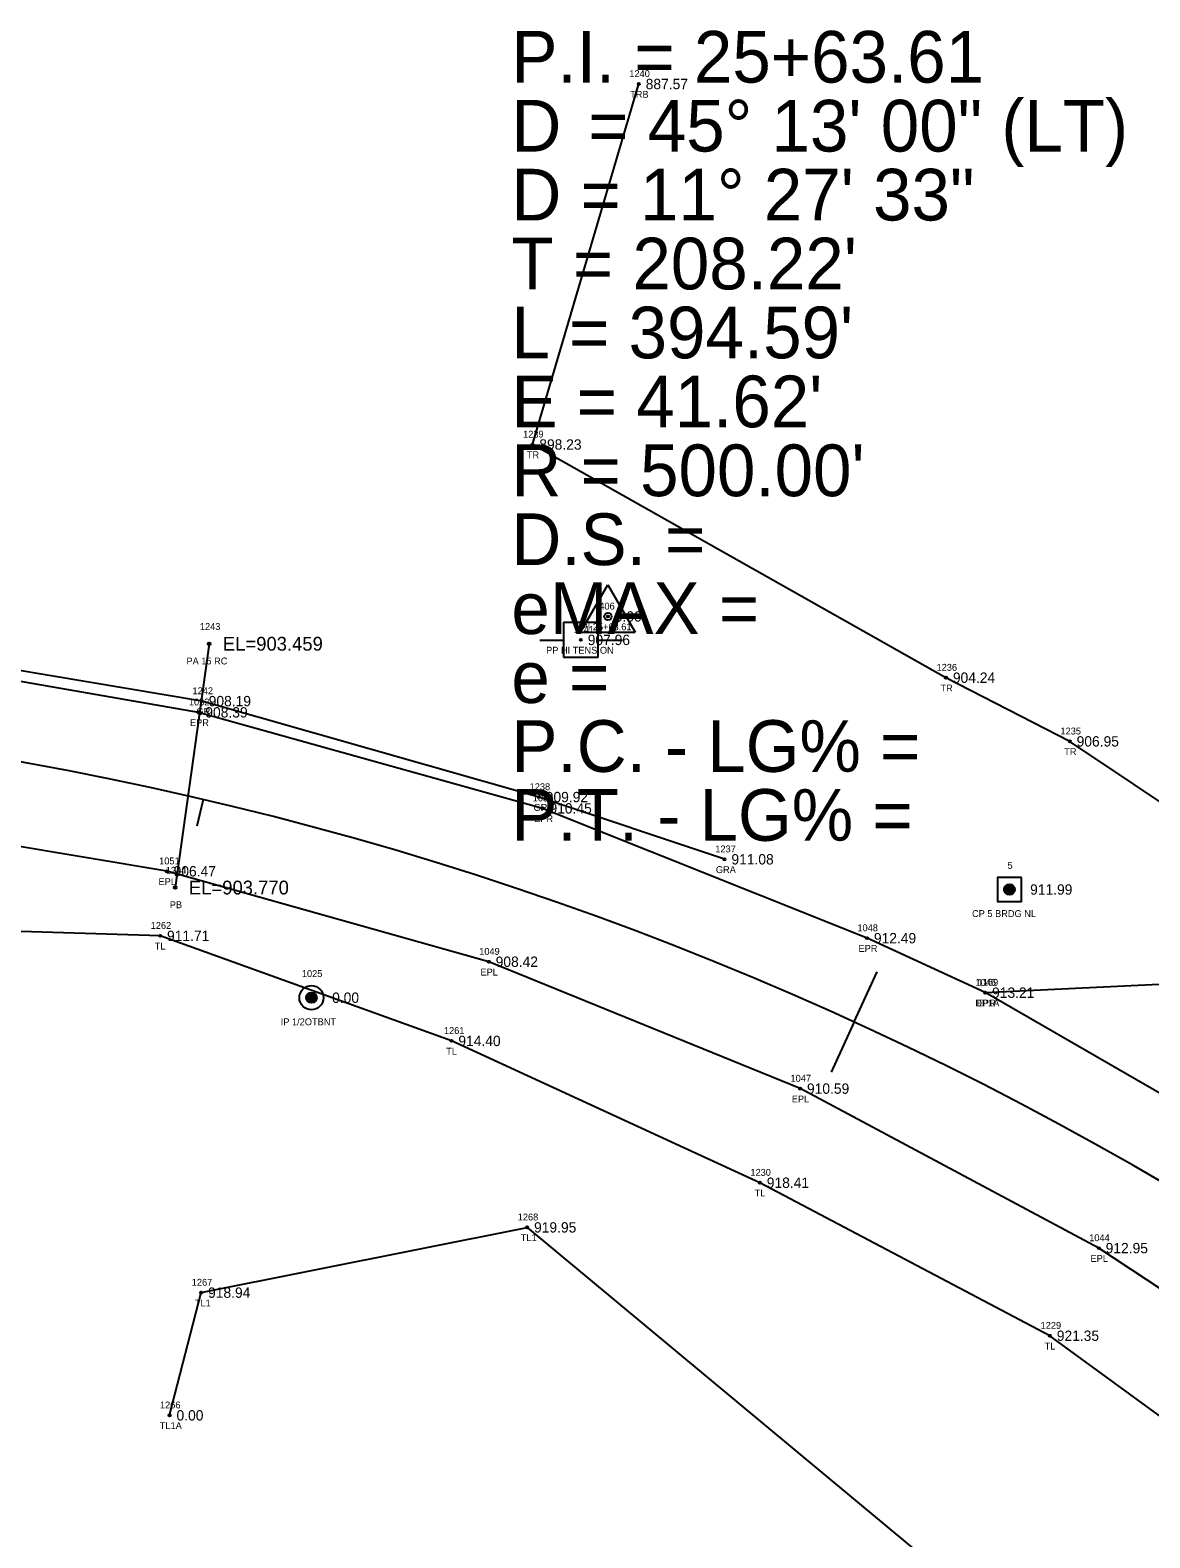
# Model space of a CAD drawing. Extents: x 1393163 to 1398407, y 1072670 to 1074651.
# Drawn here: x 1396650.2 to 1396812.6, y 1074266.9 to 1074485.6 of the extents above; entities that cross this region are included whole.
import ezdxf

# ---------------------------------------------------------------- set-up
doc = ezdxf.new("R2010")
doc.units = 0
for name, color, linetype in [('RD_EX_DR_Pipe', 7, 'Continuous'), ('RD_EX_DR_Pipe_txCode', 7, 'Continuous'), ('RD_EX_Driveway', 7, 'Continuous'), ('RD_EX_Driveway_txCode', 7, 'Continuous'), ('RD_EX_DV_Prop_txCode', 7, 'Continuous'), ('RD_EX_DV_PropPin', 7, 'Continuous'), ('RD_EX_GuardRail', 7, 'Continuous'), ('RD_EX_GuardRail_txCode', 7, 'Continuous'), ('RD_EX_Road', 7, 'Continuous'), ('RD_EX_Road_txCode', 7, 'Continuous'), ('RD_EX_TX_Driveway_ELEV', 7, 'Continuous'), ('RD_EX_TX_DV_Prop_ELEV', 7, 'Continuous'), ('RD_EX_TX_GuardRail_ELEV', 7, 'Continuous'), ('RD_EX_TX_Road_ELEV', 7, 'Continuous'), ('RD_EX_TX_VEG_ELEV', 7, 'Continuous'), ('RD_EX_UT', 7, 'Continuous'), ('RD_EX_UT_txCode', 7, 'Continuous'), ('RD_EX_VEG', 7, 'Continuous'), ('RD_EX_VEG_txCode', 7, 'Continuous'), ('RD_HC_Cl', 7, 'Continuous'), ('RD_HC_Data', 7, 'Continuous'), ('RD_HC_Data_Tic', 7, 'Continuous'), ('RD_HC_Survey', 7, 'Continuous'), ('RD_HC_Survey_ELEV', 7, 'Continuous'), ('RD_HC_Survey_txCode', 7, 'Continuous'), ('RD_HC_txCode', 7, 'Continuous'), ('RD_SMD_Locator', 7, 'Continuous'), ('RD_TX_Pipe_ElevEX', 7, 'Continuous')]:
    doc.layers.add(name, color=color, linetype=linetype)

msp = doc.modelspace()

# ---------------------------------------------------------------- linework, layer by layer
at = {"layer": 'RD_EX_DR_Pipe'}
msp.add_line((1396676.14, 1074396.59), (1396671.21, 1074361.22), dxfattribs=at)
at = {"layer": 'RD_EX_Driveway'}
msp.add_lwpolyline([(1396788.75, 1074345.97), (1396814, 1074347.19), (1396845.44, 1074351.21), (1396872.44, 1074348.53), (1396900.89, 1074337.89), (1396935.17, 1074321.37), (1396975.52, 1074301.17), (1397009.08, 1074288.99), (1397048.05, 1074289.01)], dxfattribs=at)
at = {"layer": 'RD_EX_DV_PropPin'}
for p, q in [((1396690.25, 1074345.04), (1396690.25, 1074345.43)), ((1396690.29, 1074344.94), (1396690.29, 1074345.53)), ((1396690.32, 1074344.87), (1396690.32, 1074345.61)), ((1396690.36, 1074344.81), (1396690.36, 1074345.66)), ((1396690.39, 1074344.76), (1396690.39, 1074345.71)), ((1396690.43, 1074344.72), (1396690.43, 1074345.75)), ((1396690.46, 1074344.69), (1396690.46, 1074345.79)), ((1396690.5, 1074344.65), (1396690.5, 1074345.82)), ((1396690.53, 1074344.63), (1396690.53, 1074345.85)), ((1396690.57, 1074344.6), (1396690.57, 1074345.87)), ((1396690.6, 1074344.58), (1396690.6, 1074345.89)), ((1396690.64, 1074344.56), (1396690.64, 1074345.91)), ((1396690.67, 1074344.54), (1396690.67, 1074345.93)), ((1396690.71, 1074344.53), (1396690.71, 1074345.94)), ((1396690.74, 1074344.52), (1396690.74, 1074345.96)), ((1396690.78, 1074344.5), (1396690.78, 1074345.97)), ((1396690.81, 1074344.5), (1396690.81, 1074345.98)), ((1396690.85, 1074344.49), (1396690.85, 1074345.98)), ((1396690.88, 1074344.48), (1396690.88, 1074345.99)), ((1396690.92, 1074344.48), (1396690.92, 1074345.99)), ((1396690.95, 1074344.48), (1396690.95, 1074346)), ((1396690.99, 1074344.47), (1396690.99, 1074346)), ((1396691.02, 1074344.48), (1396691.02, 1074346)), ((1396691.06, 1074344.48), (1396691.06, 1074345.99)), ((1396691.1, 1074344.48), (1396691.1, 1074345.99)), ((1396691.13, 1074344.49), (1396691.13, 1074345.98)), ((1396691.17, 1074344.5), (1396691.17, 1074345.98)), ((1396691.2, 1074344.5), (1396691.2, 1074345.97)), ((1396691.24, 1074344.52), (1396691.24, 1074345.96)), ((1396691.27, 1074344.53), (1396691.27, 1074345.94)), ((1396691.31, 1074344.54), (1396691.31, 1074345.93)), ((1396691.34, 1074344.56), (1396691.34, 1074345.91)), ((1396691.38, 1074344.58), (1396691.38, 1074345.89)), ((1396691.41, 1074344.6), (1396691.41, 1074345.87)), ((1396691.45, 1074344.63), (1396691.45, 1074345.85)), ((1396691.48, 1074344.65), (1396691.48, 1074345.82)), ((1396691.52, 1074344.69), (1396691.52, 1074345.79)), ((1396691.55, 1074344.72), (1396691.55, 1074345.75)), ((1396691.59, 1074344.76), (1396691.59, 1074345.71)), ((1396691.62, 1074344.81), (1396691.62, 1074345.66)), ((1396691.66, 1074344.87), (1396691.66, 1074345.61)), ((1396691.69, 1074344.94), (1396691.69, 1074345.53)), ((1396691.73, 1074345.04), (1396691.73, 1074345.43))]:
    msp.add_line(p, q, dxfattribs=at)
for radius in [1.75, 0.761]:
    msp.add_circle((1396690.99, 1074345.24), radius, dxfattribs=at)
at = {"layer": 'RD_EX_GuardRail'}
msp.add_lwpolyline([(1396750.93, 1074365.32), (1396723.99, 1074374.35), (1396675.08, 1074388.27), (1396625.55, 1074396.6), (1396572.93, 1074399.71), (1396523.21, 1074399.14), (1396473.17, 1074396.16), (1396421.53, 1074392.08), (1396371.98, 1074385.73), (1396321.51, 1074375.41), (1396279.87, 1074364.31)], dxfattribs=at)
at = {"layer": 'RD_EX_Road'}
for points in [[(1397127.02, 1074075.08), (1397087.96, 1074107.09), (1397050.33, 1074139.1), (1397012.08, 1074172.65), (1396975.18, 1074205.06), (1396938.56, 1074237.05), (1396899.33, 1074270.29), (1396859.1, 1074302.06), (1396826.71, 1074324.07), (1396788.75, 1074345.97), (1396771.6, 1074353.88), (1396724.53, 1074372.71), (1396674.59, 1074386.64), (1396624.89, 1074395.26)], [(1397113.03, 1074055.78), (1397073.45, 1074088.2), (1397033.12, 1074122.53), (1397005.07, 1074146.99), (1396959.64, 1074187.05), (1396921.5, 1074220.1), (1396884.1, 1074252.26), (1396844.62, 1074282.93), (1396805.23, 1074308.91), (1396761.89, 1074332.05), (1396716.72, 1074350.46), (1396669.99, 1074363.58), (1396621.68, 1074371.65)]]:
    msp.add_lwpolyline(points, dxfattribs=at)
at = {"layer": 'RD_EX_UT'}
for p, q in [((1396732.57, 1074399.66), (1396727.57, 1074399.66)), ((1396727.57, 1074399.66), (1396727.57, 1074394.66)), ((1396732.57, 1074394.66), (1396732.57, 1074399.66)), ((1396724.14, 1074397.1), (1396727.61, 1074397.1)), ((1396732.5, 1074397.1), (1396736.14, 1074397.1)), ((1396727.57, 1074394.66), (1396732.57, 1074394.66))]:
    msp.add_line(p, q, dxfattribs=at)
at = {"layer": 'RD_EX_VEG'}
for points in [[(1397009.65, 1074291.54), (1396903.78, 1074340.47), (1396857.31, 1074355.57), (1396838.07, 1074357.65), (1396801.02, 1074382.43), (1396783.06, 1074391.67), (1396723.05, 1074425.5), (1396738.49, 1074477.8)], [(1396894.17, 1074168.98), (1396933.03, 1074155.57), (1396955.02, 1074151.42), (1396964.49, 1074163.23), (1396875.81, 1074239.54), (1396798.14, 1074296.2), (1396756.06, 1074318.4), (1396711.3, 1074338.97), (1396669.03, 1074354.22), (1396616.02, 1074355.85)], [(1396670.41, 1074284.65), (1396674.99, 1074302.45), (1396722.29, 1074311.92), (1396894.17, 1074168.98)]]:
    msp.add_lwpolyline(points, dxfattribs=at)
at = {"layer": 'RD_HC_Cl'}
msp.add_arc((1396561.57, 1073887.11), 500, 48.8271, 94.0437, dxfattribs=at)
at = {"layer": 'RD_HC_Data'}
for p, q in [((1396730.03, 1074398.26), (1396734.01, 1074405.14)), ((1396734.01, 1074405.14), (1396737.97, 1074398.26)), ((1396730.03, 1074398.26), (1396737.97, 1074398.26))]:
    msp.add_line(p, q, dxfattribs=at)
msp.add_circle((1396734.01, 1074400.55), 0.529, dxfattribs=at)
at = {"layer": 'RD_HC_Data_Tic'}
for p, q in [((1396675.26, 1074374.01), (1396674.35, 1074370.12)), ((1396769.73, 1074341.72), (1396773.06, 1074348.99)), ((1396769.73, 1074341.72), (1396766.4, 1074334.45))]:
    msp.add_line(p, q, dxfattribs=at)
at = {"layer": 'RD_HC_Survey'}
for p, q in [((1396791.52, 1074360.76), (1396791.52, 1074361.12)), ((1396791.55, 1074360.68), (1396791.55, 1074361.2)), ((1396791.57, 1074360.62), (1396791.57, 1074361.26)), ((1396791.6, 1074360.57), (1396791.6, 1074361.31)), ((1396791.62, 1074360.53), (1396791.62, 1074361.36)), ((1396791.64, 1074360.49), (1396791.64, 1074361.39)), ((1396791.67, 1074360.46), (1396791.67, 1074361.42)), ((1396791.69, 1074360.43), (1396791.69, 1074361.45)), ((1396791.72, 1074360.4), (1396791.72, 1074361.48)), ((1396791.74, 1074360.38), (1396791.74, 1074361.5)), ((1396791.77, 1074360.36), (1396791.77, 1074361.53)), ((1396791.79, 1074360.34), (1396791.79, 1074361.55)), ((1396791.82, 1074360.32), (1396791.82, 1074361.57)), ((1396791.84, 1074360.3), (1396791.84, 1074361.58)), ((1396791.87, 1074360.29), (1396791.87, 1074361.6)), ((1396791.89, 1074360.27), (1396791.89, 1074361.61)), ((1396791.92, 1074360.26), (1396791.92, 1074361.63)), ((1396791.94, 1074360.25), (1396791.94, 1074361.64)), ((1396791.97, 1074360.23), (1396791.97, 1074361.65)), ((1396791.99, 1074360.22), (1396791.99, 1074361.66)), ((1396792.02, 1074360.22), (1396792.02, 1074361.67)), ((1396792.04, 1074360.21), (1396792.04, 1074361.68)), ((1396792.07, 1074360.2), (1396792.07, 1074361.68)), ((1396792.09, 1074360.19), (1396792.09, 1074361.69)), ((1396792.12, 1074360.19), (1396792.12, 1074361.7)), ((1396792.14, 1074360.18), (1396792.14, 1074361.7)), ((1396792.16, 1074360.18), (1396792.16, 1074361.7)), ((1396792.19, 1074360.18), (1396792.19, 1074361.71)), ((1396792.21, 1074360.17), (1396792.21, 1074361.71)), ((1396792.24, 1074360.17), (1396792.24, 1074361.71)), ((1396792.26, 1074360.17), (1396792.26, 1074361.71)), ((1396792.29, 1074360.17), (1396792.29, 1074361.71)), ((1396792.31, 1074360.17), (1396792.31, 1074361.71)), ((1396792.34, 1074360.18), (1396792.34, 1074361.71)), ((1396792.36, 1074360.18), (1396792.36, 1074361.71)), ((1396792.39, 1074360.18), (1396792.39, 1074361.7)), ((1396792.41, 1074360.19), (1396792.41, 1074361.7)), ((1396792.44, 1074360.19), (1396792.44, 1074361.69)), ((1396792.46, 1074360.2), (1396792.46, 1074361.69)), ((1396792.49, 1074360.2), (1396792.49, 1074361.68)), ((1396792.51, 1074360.21), (1396792.51, 1074361.67)), ((1396792.54, 1074360.22), (1396792.54, 1074361.66)), ((1396792.56, 1074360.23), (1396792.56, 1074361.65)), ((1396792.59, 1074360.24), (1396792.59, 1074361.64)), ((1396792.61, 1074360.25), (1396792.61, 1074361.63)), ((1396792.63, 1074360.27), (1396792.63, 1074361.62)), ((1396792.66, 1074360.28), (1396792.66, 1074361.61)), ((1396792.68, 1074360.29), (1396792.68, 1074361.59)), ((1396792.71, 1074360.31), (1396792.71, 1074361.57)), ((1396792.73, 1074360.33), (1396792.73, 1074361.56)), ((1396792.76, 1074360.35), (1396792.76, 1074361.54)), ((1396792.78, 1074360.37), (1396792.78, 1074361.52)), ((1396792.81, 1074360.39), (1396792.81, 1074361.49)), ((1396792.83, 1074360.42), (1396792.83, 1074361.47)), ((1396792.86, 1074360.45), (1396792.86, 1074361.44)), ((1396792.88, 1074360.48), (1396792.88, 1074361.41)), ((1396792.91, 1074360.51), (1396792.91, 1074361.37)), ((1396792.93, 1074360.55), (1396792.93, 1074361.33)), ((1396792.96, 1074360.6), (1396792.96, 1074361.29)), ((1396792.98, 1074360.65), (1396792.98, 1074361.23)), ((1396793.01, 1074360.72), (1396793.01, 1074361.16)), ((1396793.03, 1074360.83), (1396793.03, 1074361.05))]:
    msp.add_line(p, q, dxfattribs=at)
msp.add_lwpolyline([(1396794.02, 1074362.69), (1396790.52, 1074362.69), (1396790.52, 1074359.19), (1396794.02, 1074359.19)], close=True, dxfattribs=at)
msp.add_circle((1396792.27, 1074360.94), 0.769, dxfattribs=at)
at = {"layer": 'RD_SMD_Locator'}
for centre, radius in [((1396738.49, 1074477.8), 0.15), ((1396723.05, 1074425.5), 0.15), ((1396734.01, 1074400.55), 0.15), ((1396730.08, 1074397.15), 0.15), ((1396676.14, 1074396.59), 0.2), ((1396783.06, 1074391.67), 0.15), ((1396675.08, 1074388.27), 0.15), ((1396674.59, 1074386.64), 0.15), ((1396801.02, 1074382.43), 0.15), ((1396723.99, 1074374.35), 0.15), ((1396724.53, 1074372.71), 0.15), ((1396750.93, 1074365.32), 0.15), ((1396669.99, 1074363.58), 0.15), ((1396671.21, 1074361.22), 0.2), ((1396792.27, 1074360.94), 0.15), ((1396669.03, 1074354.22), 0.15), ((1396771.6, 1074353.88), 0.15), ((1396716.72, 1074350.46), 0.15), ((1396690.99, 1074345.24), 0.15), ((1396788.75, 1074345.97), 0.15), ((1396788.75, 1074345.97), 0.15), ((1396711.3, 1074338.97), 0.15), ((1396761.89, 1074332.05), 0.15), ((1396756.06, 1074318.4), 0.15), ((1396722.29, 1074311.92), 0.15), ((1396805.23, 1074308.91), 0.15), ((1396674.99, 1074302.45), 0.15), ((1396798.14, 1074296.2), 0.15), ((1396670.41, 1074284.65), 0.15)]:
    msp.add_circle(centre, radius, dxfattribs=at)

# ---------------------------------------------------------------- texts
at = {"layer": 'RD_EX_DR_Pipe_txCode'}
for s, p in [('1243', (1396674.8, 1074398.59)), ('PA 15 RC', (1396672.85, 1074393.59)), ('1244', (1396669.86, 1074363.22)), ('PB', (1396670.43, 1074358.22))]:
    msp.add_text(s, height=1, dxfattribs=at).set_placement(p)
at = {"layer": 'RD_EX_Driveway_txCode'}
for s, p in [('1169', (1396787.66, 1074346.97)), ('DP1A', (1396787.31, 1074343.97))]:
    msp.add_text(s, height=1, dxfattribs=at).set_placement(p)
at = {"layer": 'RD_EX_DV_Prop_txCode'}
for s, p in [('1025', (1396689.6, 1074348.24)), ('IP 1/2OTBNT', (1396686.53, 1074341.24))]:
    msp.add_text(s, height=1, dxfattribs=at).set_placement(p)
at = {"layer": 'RD_EX_GuardRail_txCode'}
for s, p in [('1242', (1396673.73, 1074389.27)), ('GR', (1396674.3, 1074386.27)), ('1238', (1396722.65, 1074375.35)), ('GR', (1396723.21, 1074372.35)), ('1237', (1396749.59, 1074366.32)), ('GRA', (1396749.67, 1074363.32))]:
    msp.add_text(s, height=1, dxfattribs=at).set_placement(p)
at = {"layer": 'RD_EX_Road_txCode'}
for s, p in [('1052', (1396673.2, 1074387.64)), ('EPR', (1396673.36, 1074384.64)), ('1050', (1396723.1, 1074373.71)), ('EPR', (1396723.3, 1074370.71)), ('1051', (1396668.89, 1074364.58)), ('EPL', (1396668.79, 1074361.58)), ('1048', (1396770.21, 1074354.88)), ('1049', (1396715.33, 1074351.46)), ('EPR', (1396770.37, 1074351.88)), ('EPL', (1396715.51, 1074348.46)), ('1046', (1396787.34, 1074346.97)), ('EPR', (1396787.52, 1074343.97)), ('1047', (1396760.5, 1074333.05)), ('EPL', (1396760.68, 1074330.05)), ('1044', (1396803.84, 1074309.91)), ('EPL', (1396804.03, 1074306.91))]:
    msp.add_text(s, height=1, dxfattribs=at).set_placement(p)
at = {"layer": 'RD_EX_TX_Driveway_ELEV'}
msp.add_text('913.21', height=1.5, dxfattribs=at).set_placement((1396789.75, 1074345.22))
at = {"layer": 'RD_EX_TX_DV_Prop_ELEV'}
msp.add_text('0.00', height=1.5, dxfattribs=at).set_placement((1396693.99, 1074344.49))
at = {"layer": 'RD_EX_TX_GuardRail_ELEV'}
for s, p in [('908.19', (1396676.08, 1074387.52)), ('909.92', (1396724.99, 1074373.6)), ('911.08', (1396751.93, 1074364.57))]:
    msp.add_text(s, height=1.5, dxfattribs=at).set_placement(p)
at = {"layer": 'RD_EX_TX_Road_ELEV'}
for s, p in [('908.39', (1396675.59, 1074385.89)), ('910.45', (1396725.53, 1074371.96)), ('906.47', (1396670.99, 1074362.83)), ('912.49', (1396772.6, 1074353.13)), ('908.42', (1396717.72, 1074349.71)), ('913.21', (1396789.75, 1074345.22)), ('910.59', (1396762.89, 1074331.3)), ('912.95', (1396806.23, 1074308.16))]:
    msp.add_text(s, height=1.5, dxfattribs=at).set_placement(p)
at = {"layer": 'RD_EX_TX_VEG_ELEV'}
for s, p in [('887.57', (1396739.49, 1074477.05)), ('898.23', (1396724.05, 1074424.75)), ('904.24', (1396784.06, 1074390.92)), ('906.95', (1396802.02, 1074381.68)), ('911.71', (1396670.03, 1074353.47)), ('914.40', (1396712.3, 1074338.22)), ('918.41', (1396757.06, 1074317.65)), ('919.95', (1396723.29, 1074311.17)), ('918.94', (1396675.99, 1074301.7)), ('921.35', (1396799.14, 1074295.45)), ('0.00', (1396671.41, 1074283.9))]:
    msp.add_text(s, height=1.5, dxfattribs=at).set_placement(p)
at = {"layer": 'RD_EX_UT_txCode'}
for s, p in [('1241', (1396729.02, 1074398.15)), ('PP HI TENSION', (1396725.04, 1074395.15))]:
    msp.add_text(s, height=1, dxfattribs=at).set_placement(p)
at = {"layer": 'RD_EX_VEG_txCode'}
for s, p in [('1240', (1396737.11, 1074478.8)), ('TRB', (1396737.23, 1074475.8)), ('1239', (1396721.7, 1074426.5)), ('TR', (1396722.25, 1074423.5)), ('1236', (1396781.69, 1074392.67)), ('TR', (1396782.26, 1074389.67)), ('1235', (1396799.67, 1074383.43)), ('TR', (1396800.22, 1074380.43)), ('1262', (1396667.66, 1074355.22)), ('TL', (1396668.25, 1074352.22)), ('1261', (1396710.21, 1074339.97)), ('TL', (1396710.53, 1074336.97)), ('1230', (1396754.68, 1074319.4)), ('TL', (1396755.29, 1074316.4)), ('1268', (1396720.92, 1074312.92)), ('TL1', (1396721.36, 1074309.92)), ('1267', (1396673.62, 1074303.45)), ('TL1', (1396674.06, 1074300.45)), ('1229', (1396796.79, 1074297.2)), ('TL', (1396797.37, 1074294.2)), ('1266', (1396669.01, 1074285.65)), ('TL1A', (1396668.98, 1074282.65))]:
    msp.add_text(s, height=1, dxfattribs=at).set_placement(p)
at = {"layer": 'RD_HC_Data'}
for s, p in [('P.I. = 25+63.61', (1396720, 1074478)), ('    = 45%%d 13\' 00" (LT)', (1396720, 1074468)), ('D', (1396720, 1074468)), ('D = 11%%d 27\' 33"', (1396720, 1074458)), ("T = 208.22'", (1396720, 1074448)), ("L = 394.59'", (1396720, 1074438)), ("E = 41.62'", (1396720, 1074428)), ("R = 500.00'", (1396720, 1074418)), ('D.S. = ', (1396720, 1074408)), ('eMAX = ', (1396720, 1074398)), ('e = ', (1396720, 1074388)), ('P.C. - LG% = ', (1396720, 1074378)), ('P.T. - LG% = ', (1396720, 1074368))]:
    msp.add_text(s, height=7.5, dxfattribs=at).set_placement(p)
at = {"layer": 'RD_HC_Survey_ELEV'}
for s, p in [('0.00', (1396735.01, 1074399.8)), ('907.96', (1396731.08, 1074396.4)), ('911.99', (1396795.27, 1074360.19))]:
    msp.add_text(s, height=1.5, dxfattribs=at).set_placement(p)
at = {"layer": 'RD_HC_Survey_txCode'}
for s, p in [('5', (1396791.99, 1074363.94)), ('CP 5 BRDG NL', (1396786.84, 1074356.94))]:
    msp.add_text(s, height=1, dxfattribs=at).set_placement(p)
at = {"layer": 'RD_HC_txCode'}
for s, p in [('406', (1396732.76, 1074401.55)), ('PI 25+63.61', (1396730.18, 1074398.55))]:
    msp.add_text(s, height=1, dxfattribs=at).set_placement(p)
at = {"layer": 'RD_TX_Pipe_ElevEX'}
for s, p in [('EL=903.459', (1396678.14, 1074395.59)), ('EL=903.770', (1396673.21, 1074360.22))]:
    msp.add_text(s, height=2, dxfattribs=at).set_placement(p)

doc.saveas('drawing.dxf')
